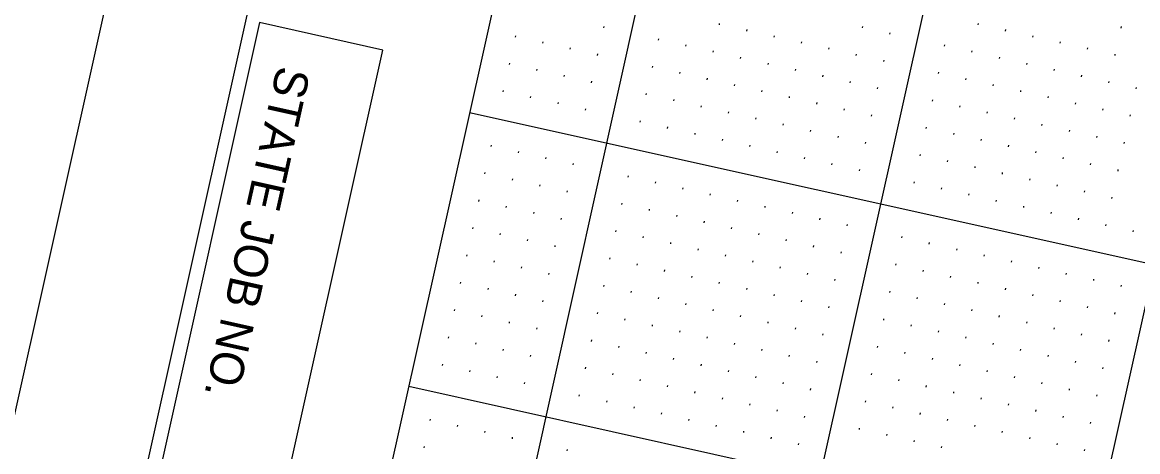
# Model space of a CAD drawing. Extents: x 2149268 to 2150830, y 142155 to 144285.
# Drawn here: x 2149373.2 to 2149571.9, y 142603.7 to 142680.3 of the extents above; entities that cross this region are included whole.
import ezdxf

# ---------------------------------------------------------------- set-up
doc = ezdxf.new("R2010")
doc.units = 0
for name, color, linetype in [('SHT_Plan_Profile_Sheet_Txt', 7, 'Continuous'), ('SHT_Plot_Shape_Half', 7, 'Continuous'), ('SHT_Profile_Grid_Major', 7, 'Continuous'), ('SHT_Profile_Grid_Minor', 7, 'Continuous'), ('SHT_Sheet_Border', 7, 'Continuous')]:
    doc.layers.add(name, color=color, linetype=linetype)

msp = doc.modelspace()

# ---------------------------------------------------------------- linework, layer by layer
at = {"layer": 'SHT_Plot_Shape_Half'}
msp.add_lwpolyline([(2150772.24, 143840.86), (2150403.25, 142181.39), (2149329.47, 142420.15), (2149698.47, 144079.62)], close=True, dxfattribs=at)
at = {"layer": 'SHT_Profile_Grid_Major'}
for p, q in [((2149767.6, 143964.37), (2149425.74, 142426.92)), ((2149816.41, 143953.52), (2149474.54, 142416.07)), ((2149865.21, 143942.67), (2149523.35, 142405.21)), ((2149452.88, 142664.18), (2149892.23, 142566.49)), ((2149442.03, 142615.38), (2149881.38, 142517.68))]:
    msp.add_line(p, q, dxfattribs=at)
at = {"layer": 'SHT_Profile_Grid_Minor'}
for p, q in [((2149476.77, 142679.49), (2149476.72, 142679.24)), ((2149497.38, 142680.03), (2149497.33, 142679.78)), ((2149502.26, 142678.94), (2149502.21, 142678.7)), ((2149522.87, 142679.48), (2149522.82, 142679.24)), ((2149527.75, 142678.4), (2149527.7, 142678.15)), ((2149543.48, 142680.02), (2149543.43, 142679.78)), ((2149548.36, 142678.94), (2149548.31, 142678.69)), ((2149568.97, 142679.48), (2149568.91, 142679.23)), ((2149461.05, 142677.86), (2149460.99, 142677.62)), ((2149465.93, 142676.78), (2149465.87, 142676.53)), ((2149486.53, 142677.32), (2149486.48, 142677.07)), ((2149507.14, 142677.86), (2149507.09, 142677.61)), ((2149512.02, 142676.77), (2149511.97, 142676.53)), ((2149553.24, 142677.85), (2149553.19, 142677.61)), ((2149558.12, 142676.77), (2149558.07, 142676.52)), ((2149470.81, 142675.69), (2149470.75, 142675.45)), ((2149475.69, 142674.61), (2149475.63, 142674.36)), ((2149491.42, 142676.23), (2149491.36, 142675.99)), ((2149496.3, 142675.15), (2149496.24, 142674.9)), ((2149516.9, 142675.69), (2149516.85, 142675.44)), ((2149521.79, 142674.6), (2149521.73, 142674.36)), ((2149537.51, 142676.23), (2149537.46, 142675.98)), ((2149542.39, 142675.14), (2149542.34, 142674.9)), ((2149563, 142675.68), (2149562.95, 142675.44)), ((2149567.88, 142674.6), (2149567.83, 142674.35)), ((2149459.96, 142672.98), (2149459.91, 142672.74)), ((2149485.45, 142672.44), (2149485.4, 142672.19)), ((2149501.18, 142674.06), (2149501.12, 142673.82)), ((2149506.06, 142672.98), (2149506, 142672.73)), ((2149526.67, 142673.52), (2149526.61, 142673.27)), ((2149547.28, 142674.06), (2149547.22, 142673.81)), ((2149552.16, 142672.97), (2149552.1, 142672.73)), ((2149464.84, 142671.9), (2149464.79, 142671.65)), ((2149469.72, 142670.81), (2149469.67, 142670.57)), ((2149490.33, 142671.35), (2149490.28, 142671.11)), ((2149510.94, 142671.89), (2149510.88, 142671.65)), ((2149515.82, 142670.81), (2149515.77, 142670.56)), ((2149536.43, 142671.35), (2149536.37, 142671.1)), ((2149557.04, 142671.89), (2149556.98, 142671.64)), ((2149561.92, 142670.8), (2149561.86, 142670.56)), ((2149474.6, 142669.73), (2149474.55, 142669.48)), ((2149495.21, 142670.27), (2149495.16, 142670.02)), ((2149500.09, 142669.18), (2149500.04, 142668.94)), ((2149520.7, 142669.72), (2149520.65, 142669.48)), ((2149525.58, 142668.64), (2149525.53, 142668.39)), ((2149541.31, 142670.26), (2149541.25, 142670.02)), ((2149546.19, 142669.18), (2149546.14, 142668.93)), ((2149566.8, 142669.71), (2149566.74, 142669.47)), ((2149571.68, 142668.63), (2149571.62, 142668.39)), ((2149458.88, 142668.1), (2149458.82, 142667.86)), ((2149463.76, 142667.02), (2149463.7, 142666.77)), ((2149484.36, 142667.56), (2149484.31, 142667.31)), ((2149489.25, 142666.47), (2149489.19, 142666.23)), ((2149504.97, 142668.1), (2149504.92, 142667.85)), ((2149509.85, 142667.01), (2149509.8, 142666.77)), ((2149535.34, 142666.46), (2149535.29, 142666.22)), ((2149551.07, 142668.09), (2149551.02, 142667.85)), ((2149555.95, 142667), (2149555.9, 142666.76)), ((2149468.64, 142665.93), (2149468.58, 142665.69)), ((2149473.52, 142664.85), (2149473.46, 142664.6)), ((2149494.13, 142665.39), (2149494.07, 142665.14)), ((2149514.73, 142665.93), (2149514.68, 142665.68)), ((2149519.62, 142664.84), (2149519.56, 142664.6)), ((2149540.22, 142665.38), (2149540.17, 142665.14)), ((2149560.83, 142665.92), (2149560.78, 142665.68)), ((2149565.71, 142664.83), (2149565.66, 142664.59)), ((2149483.28, 142662.68), (2149483.22, 142662.43)), ((2149499.01, 142664.3), (2149498.95, 142664.06)), ((2149503.89, 142663.22), (2149503.83, 142662.97)), ((2149524.5, 142663.75), (2149524.44, 142663.51)), ((2149545.1, 142664.29), (2149545.05, 142664.05)), ((2149549.99, 142663.21), (2149549.93, 142662.97)), ((2149570.59, 142663.75), (2149570.54, 142663.5)), ((2149488.16, 142661.59), (2149488.11, 142661.35)), ((2149493.04, 142660.5), (2149492.99, 142660.26)), ((2149508.77, 142662.13), (2149508.71, 142661.89)), ((2149513.65, 142661.04), (2149513.59, 142660.8)), ((2149534.26, 142661.58), (2149534.2, 142661.34)), ((2149539.14, 142660.5), (2149539.08, 142660.25)), ((2149554.87, 142662.12), (2149554.81, 142661.88)), ((2149559.75, 142661.04), (2149559.69, 142660.79)), ((2149497.92, 142659.42), (2149497.87, 142659.18)), ((2149518.53, 142659.96), (2149518.48, 142659.72)), ((2149523.41, 142658.87), (2149523.36, 142658.63)), ((2149544.02, 142659.41), (2149543.96, 142659.17)), ((2149564.63, 142659.95), (2149564.57, 142659.71)), ((2149569.51, 142658.87), (2149569.45, 142658.62)), ((2149456.7, 142658.34), (2149456.65, 142658.1)), ((2149461.59, 142657.25), (2149461.53, 142657.01)), ((2149502.8, 142658.33), (2149502.75, 142658.09)), ((2149507.68, 142657.25), (2149507.63, 142657)), ((2149533.17, 142656.7), (2149533.12, 142656.46)), ((2149548.9, 142658.33), (2149548.85, 142658.08)), ((2149553.78, 142657.24), (2149553.73, 142657)), ((2149466.47, 142656.17), (2149466.41, 142655.93)), ((2149471.35, 142655.08), (2149471.29, 142654.84)), ((2149512.56, 142656.16), (2149512.51, 142655.92)), ((2149517.44, 142655.08), (2149517.39, 142654.83)), ((2149538.05, 142655.62), (2149538, 142655.37)), ((2149542.93, 142654.53), (2149542.88, 142654.29)), ((2149558.66, 142656.16), (2149558.61, 142655.91)), ((2149563.54, 142655.07), (2149563.49, 142654.83)), ((2149455.62, 142653.46), (2149455.56, 142653.22)), ((2149481.11, 142652.91), (2149481.05, 142652.67)), ((2149522.33, 142653.99), (2149522.27, 142653.75)), ((2149547.81, 142653.45), (2149547.76, 142653.2)), ((2149568.42, 142653.99), (2149568.37, 142653.74)), ((2149460.5, 142652.37), (2149460.45, 142652.13)), ((2149465.38, 142651.29), (2149465.33, 142651.04)), ((2149485.99, 142651.83), (2149485.94, 142651.58)), ((2149490.87, 142650.74), (2149490.82, 142650.5)), ((2149532.09, 142651.82), (2149532.03, 142651.58)), ((2149536.97, 142650.74), (2149536.91, 142650.49)), ((2149552.7, 142652.36), (2149552.64, 142652.12)), ((2149557.58, 142651.28), (2149557.52, 142651.03)), ((2149454.53, 142648.58), (2149454.48, 142648.33)), ((2149470.26, 142650.2), (2149470.21, 142649.96)), ((2149495.75, 142649.66), (2149495.7, 142649.41)), ((2149500.63, 142648.57), (2149500.58, 142648.33)), ((2149541.85, 142649.65), (2149541.79, 142649.41)), ((2149546.73, 142648.57), (2149546.68, 142648.32)), ((2149562.46, 142650.19), (2149562.4, 142649.95)), ((2149567.34, 142649.11), (2149567.28, 142648.86)), ((2149459.41, 142647.49), (2149459.36, 142647.25)), ((2149480.02, 142648.03), (2149479.97, 142647.79)), ((2149484.9, 142646.95), (2149484.85, 142646.7)), ((2149505.51, 142647.49), (2149505.46, 142647.24)), ((2149551.61, 142647.48), (2149551.56, 142647.24)), ((2149464.3, 142646.41), (2149464.24, 142646.16)), ((2149469.18, 142645.32), (2149469.12, 142645.08)), ((2149489.78, 142645.86), (2149489.73, 142645.62)), ((2149494.67, 142644.78), (2149494.61, 142644.53)), ((2149510.39, 142646.4), (2149510.34, 142646.16)), ((2149515.27, 142645.32), (2149515.22, 142645.07)), ((2149556.49, 142646.4), (2149556.44, 142646.15)), ((2149561.37, 142645.31), (2149561.32, 142645.07)), ((2149453.45, 142643.7), (2149453.39, 142643.45)), ((2149458.33, 142642.61), (2149458.28, 142642.37)), ((2149478.94, 142643.15), (2149478.88, 142642.91)), ((2149499.55, 142643.69), (2149499.49, 142643.45)), ((2149504.43, 142642.61), (2149504.37, 142642.36)), ((2149520.15, 142644.23), (2149520.1, 142643.99)), ((2149566.25, 142644.23), (2149566.2, 142643.98)), ((2149571.13, 142643.14), (2149571.08, 142642.9)), ((2149463.21, 142641.53), (2149463.16, 142641.28)), ((2149483.82, 142642.07), (2149483.76, 142641.82)), ((2149488.7, 142640.98), (2149488.65, 142640.74)), ((2149509.31, 142641.52), (2149509.25, 142641.28)), ((2149529.92, 142642.06), (2149529.86, 142641.82)), ((2149534.8, 142640.98), (2149534.74, 142640.73)), ((2149452.36, 142638.82), (2149452.31, 142638.57)), ((2149468.09, 142640.44), (2149468.04, 142640.2)), ((2149493.58, 142639.9), (2149493.53, 142639.65)), ((2149498.46, 142638.81), (2149498.41, 142638.57)), ((2149514.19, 142640.44), (2149514.13, 142640.19)), ((2149519.07, 142639.35), (2149519.02, 142639.11)), ((2149539.68, 142639.89), (2149539.62, 142639.65)), ((2149544.56, 142638.81), (2149544.5, 142638.56)), ((2149457.24, 142637.73), (2149457.19, 142637.49)), ((2149462.13, 142636.65), (2149462.07, 142636.4)), ((2149477.85, 142638.27), (2149477.8, 142638.03)), ((2149482.73, 142637.19), (2149482.68, 142636.94)), ((2149503.34, 142637.73), (2149503.29, 142637.48)), ((2149508.22, 142636.64), (2149508.17, 142636.4)), ((2149528.83, 142637.18), (2149528.78, 142636.94)), ((2149549.44, 142637.72), (2149549.39, 142637.48)), ((2149554.32, 142636.63), (2149554.27, 142636.39)), ((2149467.01, 142635.56), (2149466.95, 142635.32)), ((2149487.61, 142636.1), (2149487.56, 142635.86)), ((2149492.5, 142635.02), (2149492.44, 142634.77)), ((2149513.1, 142635.56), (2149513.05, 142635.31)), ((2149533.71, 142636.09), (2149533.66, 142635.85)), ((2149538.59, 142635.01), (2149538.54, 142634.77)), ((2149559.2, 142635.55), (2149559.15, 142635.31)), ((2149451.28, 142633.94), (2149451.22, 142633.69)), ((2149456.16, 142632.85), (2149456.1, 142632.61)), ((2149476.77, 142633.39), (2149476.71, 142633.15)), ((2149497.38, 142633.93), (2149497.32, 142633.69)), ((2149502.26, 142632.84), (2149502.2, 142632.6)), ((2149517.98, 142634.47), (2149517.93, 142634.23)), ((2149543.47, 142633.92), (2149543.42, 142633.68)), ((2149548.35, 142632.84), (2149548.3, 142632.59)), ((2149564.08, 142634.46), (2149564.03, 142634.22)), ((2149568.96, 142633.38), (2149568.91, 142633.13)), ((2149461.04, 142631.77), (2149460.99, 142631.52)), ((2149465.92, 142630.68), (2149465.87, 142630.44)), ((2149481.65, 142632.31), (2149481.59, 142632.06)), ((2149486.53, 142631.22), (2149486.47, 142630.98)), ((2149507.14, 142631.76), (2149507.08, 142631.52)), ((2149512.02, 142630.67), (2149511.96, 142630.43)), ((2149527.75, 142632.3), (2149527.69, 142632.06)), ((2149532.63, 142631.21), (2149532.57, 142630.97)), ((2149553.24, 142631.75), (2149553.18, 142631.51)), ((2149558.12, 142630.67), (2149558.06, 142630.42)), ((2149450.19, 142629.06), (2149450.14, 142628.81)), ((2149491.41, 142630.13), (2149491.36, 142629.89)), ((2149496.29, 142629.05), (2149496.24, 142628.81)), ((2149516.9, 142629.59), (2149516.84, 142629.35)), ((2149537.51, 142630.13), (2149537.45, 142629.88)), ((2149542.39, 142629.04), (2149542.33, 142628.8)), ((2149563, 142629.58), (2149562.94, 142629.34)), ((2149455.07, 142627.97), (2149455.02, 142627.73)), ((2149459.95, 142626.88), (2149459.9, 142626.64)), ((2149475.68, 142628.51), (2149475.63, 142628.27)), ((2149480.56, 142627.42), (2149480.51, 142627.18)), ((2149501.17, 142627.96), (2149501.12, 142627.72)), ((2149506.05, 142626.88), (2149506, 142626.63)), ((2149526.66, 142627.42), (2149526.61, 142627.17)), ((2149547.27, 142627.96), (2149547.21, 142627.71)), ((2149552.15, 142626.87), (2149552.1, 142626.63)), ((2149567.88, 142628.5), (2149567.82, 142628.25)), ((2149464.84, 142625.8), (2149464.78, 142625.56)), ((2149485.44, 142626.34), (2149485.39, 142626.1)), ((2149490.32, 142625.25), (2149490.27, 142625.01)), ((2149510.93, 142625.79), (2149510.88, 142625.55)), ((2149515.81, 142624.71), (2149515.76, 142624.46)), ((2149531.54, 142626.33), (2149531.49, 142626.09)), ((2149536.42, 142625.25), (2149536.37, 142625)), ((2149557.03, 142625.79), (2149556.98, 142625.54)), ((2149561.91, 142624.7), (2149561.86, 142624.46)), ((2149449.11, 142624.17), (2149449.05, 142623.93)), ((2149453.99, 142623.09), (2149453.93, 142622.85)), ((2149474.6, 142623.63), (2149474.54, 142623.38)), ((2149495.21, 142624.17), (2149495.15, 142623.92)), ((2149500.09, 142623.08), (2149500.03, 142622.84)), ((2149541.3, 142624.16), (2149541.25, 142623.92)), ((2149546.18, 142623.08), (2149546.13, 142622.83)), ((2149566.79, 142623.62), (2149566.74, 142623.37)), ((2149458.87, 142622), (2149458.81, 142621.76)), ((2149463.75, 142620.92), (2149463.7, 142620.67)), ((2149479.48, 142622.54), (2149479.42, 142622.3)), ((2149484.36, 142621.46), (2149484.3, 142621.21)), ((2149504.97, 142622), (2149504.91, 142621.75)), ((2149509.85, 142620.91), (2149509.79, 142620.67)), ((2149525.58, 142622.54), (2149525.52, 142622.29)), ((2149530.46, 142621.45), (2149530.4, 142621.21)), ((2149551.06, 142621.99), (2149551.01, 142621.75)), ((2149555.95, 142620.91), (2149555.89, 142620.66)), ((2149448.02, 142619.29), (2149447.97, 142619.05)), ((2149473.51, 142618.75), (2149473.46, 142618.5)), ((2149489.24, 142620.37), (2149489.18, 142620.13)), ((2149494.12, 142619.29), (2149494.07, 142619.04)), ((2149514.73, 142619.83), (2149514.67, 142619.58)), ((2149535.34, 142620.37), (2149535.28, 142620.12)), ((2149540.22, 142619.28), (2149540.16, 142619.04)), ((2149560.83, 142619.82), (2149560.77, 142619.58)), ((2149565.71, 142618.74), (2149565.65, 142618.49)), ((2149452.9, 142618.21), (2149452.85, 142617.96)), ((2149457.78, 142617.12), (2149457.73, 142616.88)), ((2149478.39, 142617.66), (2149478.34, 142617.42)), ((2149499, 142618.2), (2149498.95, 142617.96)), ((2149503.88, 142617.12), (2149503.83, 142616.87)), ((2149524.49, 142617.66), (2149524.44, 142617.41)), ((2149545.1, 142618.2), (2149545.04, 142617.95)), ((2149549.98, 142617.11), (2149549.93, 142616.87)), ((2149462.66, 142616.04), (2149462.61, 142615.79)), ((2149483.27, 142616.58), (2149483.22, 142616.33)), ((2149488.15, 142615.49), (2149488.1, 142615.25)), ((2149508.76, 142616.03), (2149508.71, 142615.79)), ((2149513.64, 142614.95), (2149513.59, 142614.7)), ((2149529.37, 142616.57), (2149529.32, 142616.33)), ((2149534.25, 142615.49), (2149534.2, 142615.24)), ((2149554.86, 142616.03), (2149554.81, 142615.78)), ((2149559.74, 142614.94), (2149559.69, 142614.7)), ((2149472.43, 142613.87), (2149472.37, 142613.62)), ((2149477.31, 142612.78), (2149477.25, 142612.54)), ((2149493.03, 142614.41), (2149492.98, 142614.16)), ((2149497.92, 142613.32), (2149497.86, 142613.08)), ((2149523.4, 142612.78), (2149523.35, 142612.53)), ((2149539.13, 142614.4), (2149539.08, 142614.16)), ((2149544.01, 142613.32), (2149543.96, 142613.07)), ((2149564.62, 142613.86), (2149564.57, 142613.61)), ((2149482.19, 142611.7), (2149482.13, 142611.45)), ((2149502.8, 142612.24), (2149502.74, 142611.99)), ((2149507.68, 142611.15), (2149507.62, 142610.91)), ((2149528.29, 142611.69), (2149528.23, 142611.45)), ((2149548.89, 142612.23), (2149548.84, 142611.99)), ((2149553.77, 142611.15), (2149553.72, 142610.9)), ((2149445.85, 142609.53), (2149445.8, 142609.29)), ((2149487.07, 142610.61), (2149487.01, 142610.37)), ((2149491.95, 142609.53), (2149491.9, 142609.28)), ((2149512.56, 142610.07), (2149512.5, 142609.82)), ((2149533.17, 142610.61), (2149533.11, 142610.36)), ((2149538.05, 142609.52), (2149537.99, 142609.28)), ((2149558.66, 142610.06), (2149558.6, 142609.82)), ((2149563.54, 142608.97), (2149563.48, 142608.73)), ((2149450.73, 142608.45), (2149450.68, 142608.2)), ((2149455.61, 142607.36), (2149455.56, 142607.12)), ((2149496.83, 142608.44), (2149496.78, 142608.2)), ((2149501.71, 142607.36), (2149501.66, 142607.11)), ((2149522.32, 142607.9), (2149522.27, 142607.65)), ((2149527.2, 142606.81), (2149527.15, 142606.57)), ((2149542.93, 142608.44), (2149542.87, 142608.19)), ((2149547.81, 142607.35), (2149547.75, 142607.11)), ((2149460.49, 142606.28), (2149460.44, 142606.03)), ((2149506.59, 142606.27), (2149506.54, 142606.03)), ((2149511.47, 142605.19), (2149511.42, 142604.94)), ((2149532.08, 142605.72), (2149532.03, 142605.48)), ((2149552.69, 142606.26), (2149552.64, 142606.02)), ((2149557.57, 142605.18), (2149557.52, 142604.94)), ((2149444.77, 142604.65), (2149444.71, 142604.41)), ((2149470.26, 142604.11), (2149470.2, 142603.86)), ((2149536.96, 142604.64), (2149536.91, 142604.4)), ((2149562.45, 142604.09), (2149562.4, 142603.85))]:
    msp.add_line(p, q, dxfattribs=at)
at = {"layer": 'SHT_Sheet_Border'}
for points in [[(2150726.67, 143751.11), (2150384.81, 142213.66), (2149359.84, 142441.57), (2149701.71, 143979.02)], [(2149437.43, 142675.3), (2149415.46, 142680.19), (2149362.83, 142443.47), (2149384.79, 142438.59)]]:
    msp.add_lwpolyline(points, close=True, dxfattribs=at)
msp.add_lwpolyline([(2149433.9, 142694.01), (2149458.31, 142688.59), (2149409.47, 142468.95)], dxfattribs=at)

# ---------------------------------------------------------------- texts
at = {"layer": 'SHT_Plan_Profile_Sheet_Txt'}
msp.add_text('STATE JOB NO.', height=6, rotation=257.4638, dxfattribs=at).set_placement((2149418.66, 142672.71))

doc.saveas('drawing.dxf')
